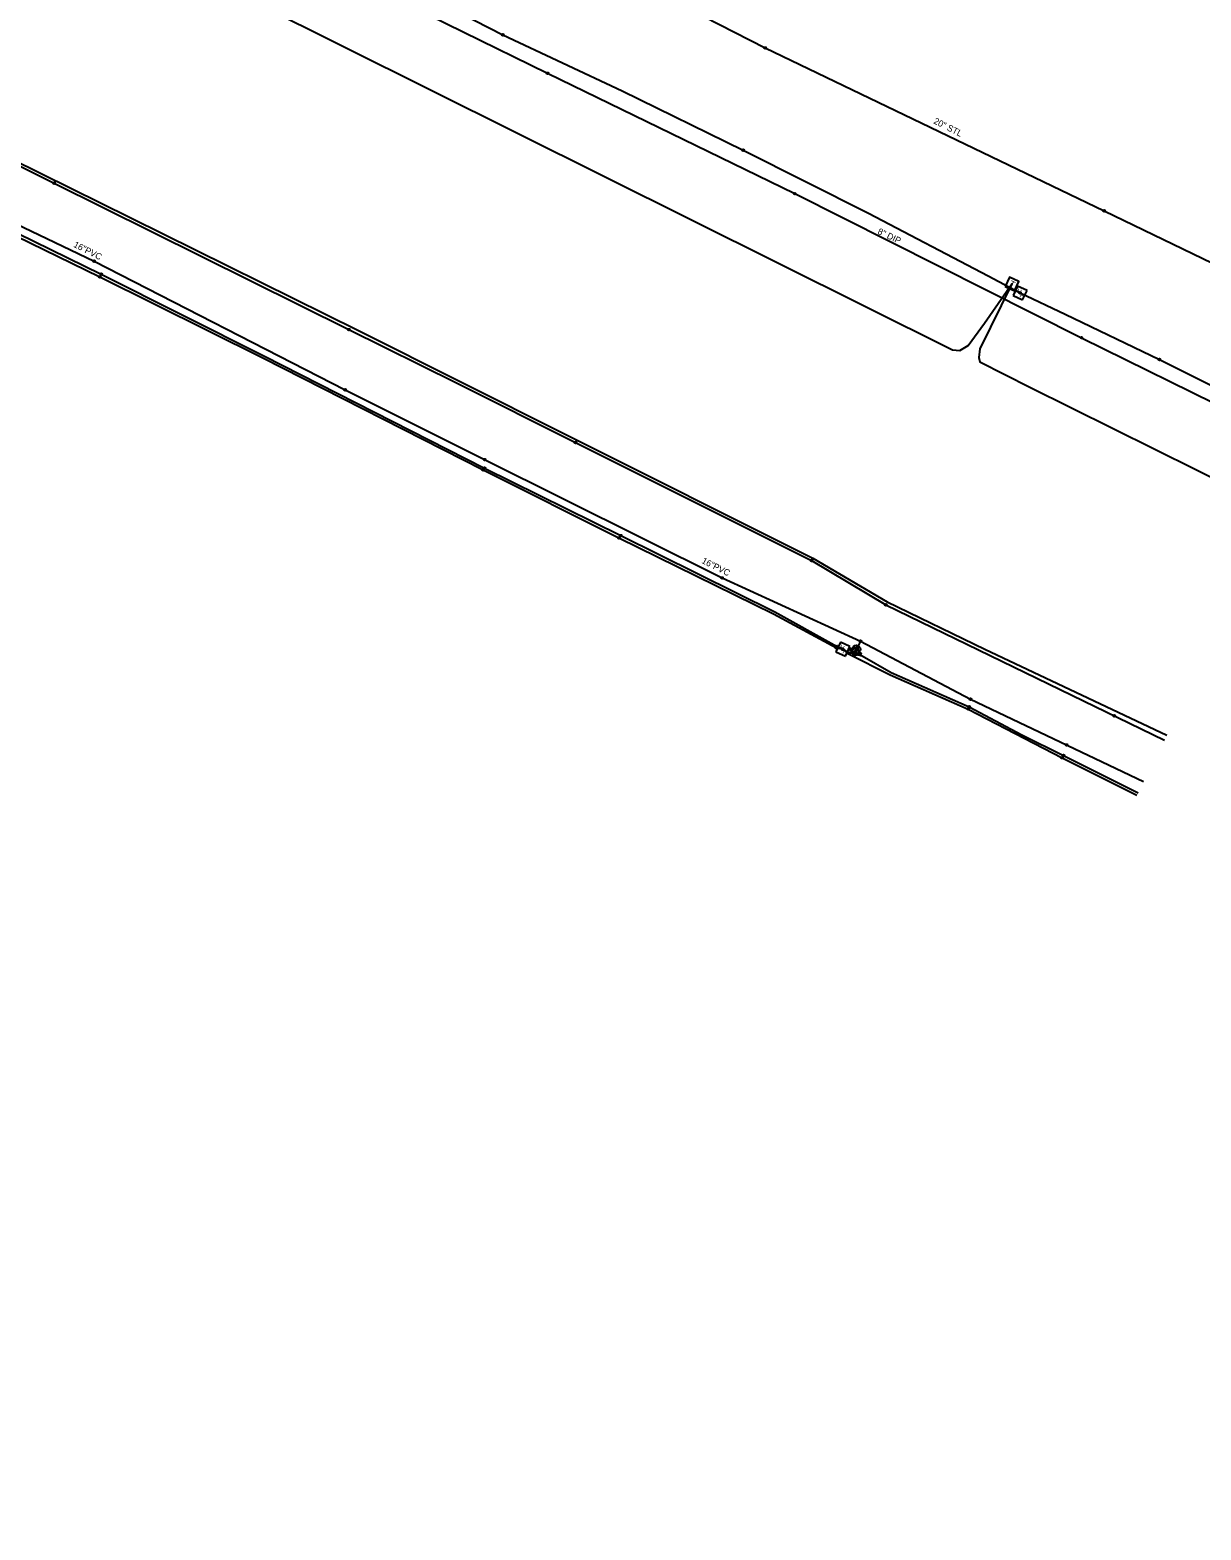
# Model space of a CAD drawing. Extents: x 2244485 to 2250986, y 199568 to 203007.
# Drawn here: x 2245928 to 2246567, y 201318 to 202136 of the extents above; entities that cross this region are included whole.
import ezdxf

# ---------------------------------------------------------------- set-up
doc = ezdxf.new("R2010")
doc.units = 0
for name, color, linetype in [('Default', 7, 'Continuous'), ('Exist Utilities Gas UG Line SUE LOS B', 7, 'Continuous'), ('Exist Utilities Gas UG Line SUE LOS B Text', 7, 'Continuous'), ('Exist Utilities Sanitary Sewer Forced Main SUE LOS B', 7, 'Continuous'), ('Exist Utilities Sanitary Sewer Forced Main SUE LOS B Text', 7, 'Continuous'), ('Exist Utilities Telephone Hand Hole CELL', 7, 'Continuous'), ('Exist Utilities Telephone Pedestal CELL', 7, 'Continuous'), ('Exist Utilities Telephone UG Cable SUE LOS C', 7, 'Continuous'), ('Exist Utilities Telephone UG FO SUE LOS B', 7, 'Continuous'), ('Exist Utilities Telephone UG FO SUE LOS C', 7, 'Continuous'), ('Exist Utilities Water Fire Hydrant CELL', 7, 'Continuous'), ('Exist Utilities Water UG Line SUE LOS B', 7, 'Continuous'), ('Exist Utilities Water UG Line SUE LOS B Text', 7, 'Continuous'), ('Exist Utilities Water Valve CELL', 7, 'Continuous')]:
    doc.layers.add(name, color=color, linetype=linetype)

# ---------------------------------------------------------------- blocks, each defined once
blk = doc.blocks.new('SurveyPointCell')
at = {"layer": 'Default'}
for p, q in [((-0.5, 0), (0.5, 0)), ((0, -0.5), (0, 0.5))]:
    blk.add_line(p, q, dxfattribs=at)
blk.add_circle((0, 0), 0.5, dxfattribs=at)

msp = doc.modelspace()

# ---------------------------------------------------------------- linework, layer by layer
at = {"layer": 'Exist Utilities Gas UG Line SUE LOS B'}
msp.add_lwpolyline([(2244658.96, 202958.49), (2244721.96, 202928.3), (2244863.47, 202856.19), (2244912.51, 202831.57), (2245070.07, 202752.33), (2245256.14, 202659.91), (2245331.4, 202622.29), (2245514.38, 202531.76), (2245606.53, 202488.05), (2245652.12, 202465.42), (2245827.69, 202375.08), (2246001.01, 202291.84), (2246162.3, 202211.17), (2246329.12, 202125.74), (2246513.99, 202036.93), (2246642.7, 201974.75), (2246734.96, 201930.33), (2246858.92, 201868.26), (2246999.42, 201799.12), (2247177.53, 201710.71), (2247331.7, 201633.3), (2247466.92, 201567.22), (2247602.4, 201501.88), (2247749.1, 201426.01)], dxfattribs=at)
at = {"layer": 'Exist Utilities Sanitary Sewer Forced Main SUE LOS B'}
msp.add_lwpolyline([(2245613.42, 202432.81), (2245612.33, 202430.62), (2245623.54, 202401.29), (2245742.14, 202343.1), (2245917.37, 202257.79), (2246026.41, 202202.34), (2246210.46, 202111.93), (2246345.24, 202046.28), (2246501.59, 201967.74), (2246585.87, 201926.12), (2246766.44, 201836.2), (2246874.3, 201784.12), (2246993.56, 201724.08), (2247186.6, 201626.85), (2247291.7, 201574.36), (2247419.93, 201509.91), (2247528.38, 201455.85), (2247631.36, 201405.97), (2247735.41, 201350.67), (2247801.59, 201317.51)], dxfattribs=at)
at = {"layer": 'Exist Utilities Telephone Hand Hole CELL'}
for p, q in [((2246466.78, 201995.92), (2246464.3, 201990.76)), ((2246471.94, 201993.45), (2246466.78, 201995.92)), ((2246469.46, 201988.29), (2246471.94, 201993.45)), ((2246464.3, 201990.76), (2246469.46, 201988.29)), ((2246468.12, 201992.1), (2246468.12, 201992.1)), ((2246370.17, 201801.67), (2246367.74, 201796.49)), ((2246375.35, 201799.24), (2246370.17, 201801.67)), ((2246371.55, 201797.86), (2246371.55, 201797.86)), ((2246372.92, 201794.05), (2246375.35, 201799.24)), ((2246367.74, 201796.49), (2246372.92, 201794.05))]:
    msp.add_line(p, q, dxfattribs=at)
at = {"layer": 'Exist Utilities Telephone Pedestal CELL'}
msp.add_line((2246463.67, 201997.05), (2246463.67, 201997.05), dxfattribs=at)
msp.add_lwpolyline([(2246459.99, 201995.69), (2246465.02, 201993.26), (2246467.46, 201998.29), (2246462.42, 202000.73), (2246459.99, 201995.69)], dxfattribs=at)
at = {"layer": 'Exist Utilities Telephone UG Cable SUE LOS C'}
msp.add_lwpolyline([(2245130.24, 202608.24), (2245342.53, 202504.23), (2245365.2, 202493.05), (2245368.49, 202493.82), (2245371.26, 202498.68), (2245389.55, 202529.63), (2245373.43, 202494.83), (2245372.62, 202491.73), (2245374.18, 202489.1), (2245390.76, 202481.45), (2245604.3, 202371.42), (2245815.4, 202267.89), (2246098.91, 202126.77), (2246431.3, 201961.17), (2246435.26, 201960.69), (2246439.92, 201963.48), (2246448.75, 201975.62), (2246463.67, 201997.05), (2246446.22, 201961.62), (2246445.59, 201956.98), (2246446.26, 201954.54), (2246473.42, 201940.75), (2246700.68, 201828.04)], dxfattribs=at)
at = {"layer": 'Exist Utilities Telephone UG FO SUE LOS B'}
for points in [[(2245297.18, 202369.62), (2245354.5, 202340.75), (2245413.57, 202314.06), (2245491.04, 202274.06), (2245523.39, 202259.78), (2245577.45, 202231.04), (2245618.81, 202209.65), (2245662.83, 202189.65), (2245702.29, 202169.93), (2245742.87, 202150.13), (2245837.39, 202103.05), (2245884.95, 202080.1), (2245941.39, 202052.03), (2246102.15, 201972.13), (2246160.8, 201943.07), (2246225.68, 201910.57), (2246354.46, 201846.2), (2246394.94, 201822.07), (2246546.85, 201748.25)], [(2245348.07, 202287.8), (2245351.12, 202288.29), (2245395.88, 202285.86), (2245429.04, 202272.44), (2245447.42, 202262.89), (2245475.01, 202247.57), (2245501.44, 202232.58), (2245544.7, 202210.01), (2245616.26, 202176.91), (2245657.32, 202158.54), (2245712.97, 202132.89), (2245773.8, 202098.67), (2245830.52, 202069.53), (2245875.55, 202047.04), (2245967.13, 202002.37), (2246055.75, 201957.91), (2246176.16, 201896.67), (2246250.38, 201859.8), (2246334.37, 201818.25), (2246368.32, 201799.38), (2246371.55, 201797.86)], [(2246123.94, 202164.93), (2246186.06, 202132.91), (2246251.2, 202102.4), (2246317.19, 202070.04), (2246385.45, 202035.61), (2246450.72, 202001.51), (2246468.14, 201992.12), (2246492.74, 201980.62), (2246544.1, 201955.85), (2246738.78, 201858.63)], [(2245656.7, 202157.5), (2245712.28, 202131.67), (2245773.13, 202097.57), (2245829.89, 202068.68), (2245874.82, 202045.43), (2245966.35, 202000.87), (2246055.16, 201956.67), (2246175.36, 201895.6), (2246249.42, 201858.51), (2246333.73, 201817.12), (2246368.01, 201798.67), (2246371.55, 201797.86), (2246374.21, 201795.47), (2246397.35, 201783.95), (2246439.89, 201765.24), (2246491.07, 201738.67), (2246531.77, 201718.23)], [(2246371.55, 201797.86), (2246374.62, 201796.22), (2246382.07, 201794.3), (2246397.84, 201785.08), (2246440.42, 201766.42), (2246469.05, 201751.2), (2246491.82, 201739.96), (2246532.5, 201719.61)]]:
    msp.add_lwpolyline(points, dxfattribs=at)
at = {"layer": 'Exist Utilities Telephone UG FO SUE LOS C'}
msp.add_lwpolyline([(2244555.09, 202740.38), (2244612.45, 202712.07), (2244680.5, 202678.83), (2244750.01, 202644.92), (2244809.78, 202614.66), (2244896.14, 202572.42), (2244969.14, 202536), (2245027.26, 202506.94), (2245218.26, 202412.25), (2245428.66, 202309.78), (2245606.8, 202219.11), (2245703.35, 202173.01), (2245852.59, 202097.7), (2245983.22, 202033.13), (2246107.4, 201971.58), (2246219.73, 201915.39), (2246355.16, 201847.48), (2246395.74, 201823.66), (2246448.95, 201797.92), (2246548.24, 201751.03)], dxfattribs=at)
at = {"layer": 'Exist Utilities Water Fire Hydrant CELL'}
msp.add_line((2246378.37, 201796.47), (2246378.37, 201796.47), dxfattribs=at)
for points in [[(2246376.82, 201797.71), (2246375.65, 201798.23), (2246375.23, 201797.29), (2246376.43, 201796.76)], [(2246379.61, 201798.01), (2246380.13, 201799.19), (2246379.19, 201799.6), (2246378.67, 201798.42)], [(2246380.32, 201796.17), (2246381.5, 201795.65), (2246381.09, 201794.71), (2246379.89, 201795.24)]]:
    msp.add_lwpolyline(points, dxfattribs=at)
for radius in [1.98, 0.243]:
    msp.add_circle((2246378.37, 201796.47), radius, dxfattribs=at)
at = {"layer": 'Exist Utilities Water UG Line SUE LOS B'}
for points in [[(2245364.27, 202308.61), (2245366.59, 202307.41), (2245381, 202297.8), (2245385.67, 202292.83), (2245395.79, 202288.35), (2245419.32, 202278.5), (2245448.28, 202263.59), (2245479.99, 202246.8), (2245504.9, 202233.28), (2245520.47, 202223.52), (2245545.35, 202213.61), (2245702.65, 202138.15), (2245808.82, 202083.18), (2245963.17, 202009.49), (2246100.08, 201939.27), (2246176.18, 201901.25), (2246305.63, 201836.71), (2246381.12, 201802.25)], [(2246381.12, 201802.25), (2246378.97, 201797.8), (2246378.37, 201796.46)], [(2246381.12, 201802.25), (2246441.13, 201770.59), (2246535.53, 201725.62)]]:
    msp.add_lwpolyline(points, dxfattribs=at)
at = {"layer": 'Exist Utilities Water Valve CELL'}
msp.add_lwpolyline([(2246380.48, 201799.32), (2246377.33, 201796.17), (2246378.91, 201797.74), (2246380.48, 201796.17), (2246377.33, 201799.32)], dxfattribs=at)
msp.add_circle((2246378.91, 201797.74), 2.23, dxfattribs=at)

# ---------------------------------------------------------------- block references
at = {"layer": 'Default'}
for p in [(2246186.06, 202132.91), (2246329.12, 202125.74), (2246210.46, 202111.93), (2246317.19, 202070.04), (2245941.39, 202052.03), (2246345.24, 202046.28), (2246513.99, 202036.93), (2245963.17, 202009.49), (2245966.35, 202000.87), (2245967.13, 202002.37), (2246468.14, 201992.12), (2246102.15, 201972.13), (2246501.59, 201967.74), (2246544.1, 201955.85), (2246100.08, 201939.27), (2246225.68, 201910.57), (2246175.36, 201895.6), (2246176.16, 201896.67), (2246176.18, 201901.25), (2246249.42, 201858.51), (2246250.38, 201859.8), (2246354.46, 201846.2), (2246305.63, 201836.71), (2246394.94, 201822.07), (2246368.01, 201798.67), (2246368.32, 201799.38), (2246371.46, 201797.78), (2246371.57, 201797.74), (2246378.37, 201796.46), (2246378.97, 201797.8), (2246381.12, 201802.25), (2246381.12, 201802.25), (2246439.89, 201765.24), (2246440.42, 201766.42), (2246441.13, 201770.59), (2246519.52, 201761.53), (2246491.82, 201739.96), (2246493.51, 201745.64), (2246491.07, 201738.67)]:
    msp.add_blockref('SurveyPointCell', p, dxfattribs=at)

# ---------------------------------------------------------------- texts
at = {"layer": 'Exist Utilities Gas UG Line SUE LOS B Text'}
msp.add_text('20" STL', height=3.5, rotation=333.09153, dxfattribs=at).set_placement((2246420.65, 202084.75))
at = {"layer": 'Exist Utilities Sanitary Sewer Forced Main SUE LOS B Text'}
msp.add_text('8" DIP', height=3.5, rotation=334.4319, dxfattribs=at).set_placement((2246390.1, 202024.5))
at = {"layer": 'Exist Utilities Telephone Hand Hole CELL'}
for rotation, p in [(334.34832, (2246465.98, 201992.47)), (334.34832, (2246467.67, 201990.04)), (334.85051, (2246369.41, 201798.21)), (334.85051, (2246371.11, 201795.79))]:
    msp.add_text('H', height=2.5, rotation=rotation, dxfattribs=at).set_placement(p)
at = {"layer": 'Exist Utilities Telephone Pedestal CELL'}
msp.add_text('T', height=3.42, rotation=334.19129, dxfattribs=at).set_placement((2246461.91, 201996))
at = {"layer": 'Exist Utilities Water UG Line SUE LOS B Text'}
for p in [(2245951.63, 202017.4), (2246294.2, 201844.99)]:
    msp.add_text('16"PVC', height=3.5, rotation=333.09153, dxfattribs=at).set_placement(p)

doc.saveas('drawing.dxf')
